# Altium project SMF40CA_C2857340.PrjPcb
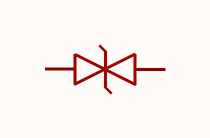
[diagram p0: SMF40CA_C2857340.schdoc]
1 sheet, 1 parts. Net scope: global (net labels, ports and power ports of the same name join across sheets).

## Sheet SMF40CA_C2857340.schdoc
size 127 x 101 mm

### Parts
D?  smf40ca_c2857340  [SOD-123FL_L2.8-W1.8-LS3.7-BI]  (value not drawn)

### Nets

Not connected (* = marked no-connect by the designer): D? 1 2

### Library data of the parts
D? = smf40ca_c2857340: 极性:双向;反向截止电压(Vrwm):40V;钳位电压:64.5V;峰值脉冲电流(Ipp):3.1A;峰值脉冲功率(Ppp):200W@10/1000us;击穿电压(VBR):44.4V;; Manufacturer: JSMSEMI(杰盛微); AddInBom: yes; ModelId: d105299b3871451c86f679efef28ff8f; ModelTransform: 145.669,70.866,0,0,0,0,0,0,0; Polarity: 双向; Reverse Stand-Off Voltage (Vrwm): 40V; Clamping Voltage: 64.5V; Peak Pulse Current (Ipp): 3.1A; Voltage - Breakdown: 44.4V; Reverse Leakage Current (Ir): 1uA; Number of Channels: 单路; Type: TVS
